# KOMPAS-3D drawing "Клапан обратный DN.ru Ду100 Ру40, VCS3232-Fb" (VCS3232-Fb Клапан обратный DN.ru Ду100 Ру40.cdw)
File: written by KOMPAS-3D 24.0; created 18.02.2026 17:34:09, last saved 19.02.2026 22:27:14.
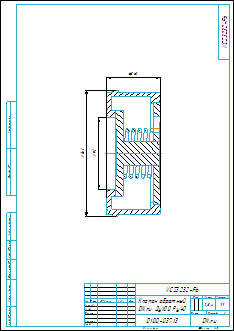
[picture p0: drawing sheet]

Document properties: v313: 1; D: 58; d: 20; a: 1; L: 28; Артикул: D100-03713; Автор: R2D2; Форматы листов документа: A3; Полное имя файла: VCS3232-Fb Клапан обратный DN.ru Ду100 Ру40.m3d; Масса: 2.84; Наименование: Клапан обратный DN.ru Ду100 Ру40; Количество листов документа: 1; Примечание: D100-03713

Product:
- Body: Тело 1  | qty 1
    Масса: 2.494534
- Body: Тело 2  | qty 1
    Масса: 1.619958
- Part/product: Клапан обратный DN.ru Ду100 Ру40  | designation VCS3232-Fb
    Масса: 2.84
    Примечание: D100-03713
    additional columns: 1; D100-03713

Views: Вид 1, Местный разрез 1, Справа
Referenced files in E:\Работа\Зайцев\VCS3232-Fb Клапан обратный DN.ru Ду15-100\DN32\: VCS3232-Fb Клапан обратный DN.ru Ду32 Ру40.m3d
Referenced files in E:\Работа\Зайцев\VCS3232-Fb Клапан обратный DN.ru Ду15-100\DN25\: VCS3232-Fb Клапан обратный DN.ru Ду25 Ру40.m3d
Referenced files in E:\Работа\Зайцев\VCS3232-Fb Клапан обратный DN.ru Ду15-100\DN100\: VCS3232-Fb Клапан обратный DN.ru Ду100 Ру40.m3d
Referenced files in E:\Работа\Зайцев\Для компаса\: чертеж DN.ru.cdt
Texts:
  VCS3232-Fb
  чертеж DN.ru.cdt
  Клапан обратный
  DN.ru Ду100 Ру40
  prop
  Клапан обратный DN.ru Ду100 Ру40
  VCS3232-Fb Клапан обратный DN.ru Ду100 Ру40
Dimensions and other numbers on the sheet: 0; 3; 2; 4; 91; 161; 68±2; 6; 1:1; 1; 2,84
